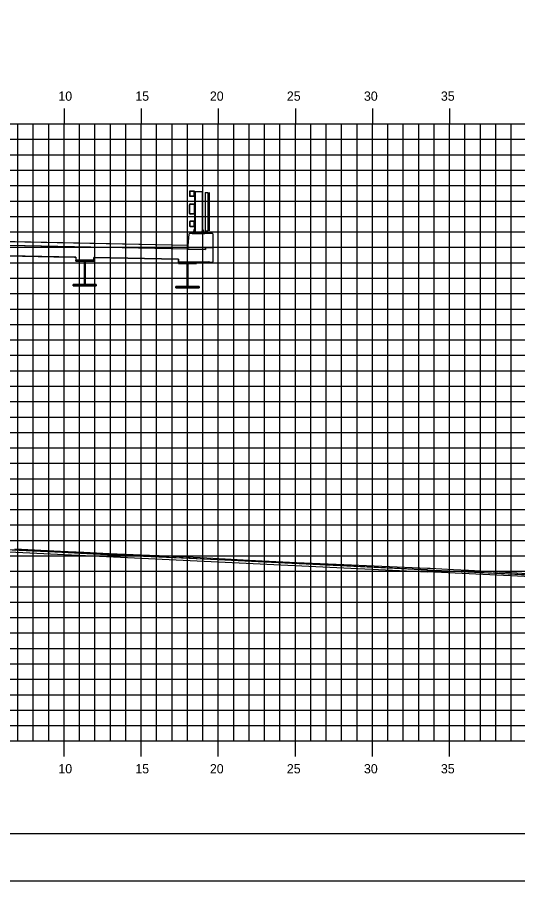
# Model space of a CAD drawing. Extents: x -22 to 1480, y -1511 to 8.
# Drawn here: x 733.2 to 765.6, y -184.5 to -128.6 of the extents above; entities that cross this region are included whole.
import ezdxf

# ---------------------------------------------------------------- set-up
doc = ezdxf.new("R2010")
doc.units = 0
for name, color, linetype in [('BORDER', 7, 'Continuous'), ('D_Bridge_Deck', 7, 'Continuous'), ('D_Bridge_Railing', 7, 'Continuous'), ('D_Bridge_Superstructure', 7, 'Continuous'), ('D_Bridge_Superstructure_Slab', 7, 'Continuous'), ('D_Roadway_Centerline', 7, 'Continuous'), ('D_Roadway_Edge_Shoulder', 7, 'Continuous'), ('D_Roadway_Edge_TW', 7, 'Continuous'), ('H_V ANNOTATION', 7, 'Continuous'), ('MAJOR', 7, 'Continuous'), ('MINOR', 7, 'Continuous'), ('PLOT BOUNDARY', 7, 'Continuous'), ('S_Roadway_Centerline', 7, 'Continuous')]:
    doc.layers.add(name, color=color, linetype=linetype)

msp = doc.modelspace()

# ---------------------------------------------------------------- linework, layer by layer
at = {"layer": 'BORDER'}
msp.add_line((651.209, -181.466), (811.209, -181.466), dxfattribs=at)
at = {"layer": 'D_Bridge_Deck'}
for p, q in [((745.376, -143.614), (745.376, -143.489)), ((745.376, -143.489), (745.834, -143.489))]:
    msp.add_line(p, q, dxfattribs=at)
for points in [[(745.834, -143.489), (745.876, -143.447), (745.876, -142.611), (745.834, -142.57), (744.334, -142.57), (744.289, -142.611), (744.209, -143.59)], [(745.584, -144.424), (744.876, -144.424), (743.626, -144.424)]]:
    msp.add_lwpolyline(points, dxfattribs=at)
at = {"layer": 'D_Bridge_Railing'}
for p, q in [((744.334, -139.861), (744.334, -140.111)), ((744.355, -139.861), (744.355, -140.111)), ((744.626, -139.82), (744.376, -139.82)), ((744.626, -139.84), (744.376, -139.84)), ((744.647, -140.111), (744.647, -139.861)), ((744.667, -140.111), (744.667, -139.861)), ((744.705, -139.861), (744.705, -142.393)), ((745.161, -139.861), (745.161, -142.393)), ((745.366, -139.903), (745.366, -142.394)), ((745.366, -139.903), (745.532, -139.903)), ((745.532, -139.903), (745.532, -142.394)), ((744.376, -140.132), (744.626, -140.132)), ((744.376, -140.153), (744.626, -140.153)), ((744.334, -141.268), (744.334, -140.705)), ((744.36, -141.268), (744.36, -140.705)), ((744.386, -140.653), (744.615, -140.653)), ((744.386, -140.679), (744.615, -140.679)), ((744.641, -140.705), (744.641, -141.268)), ((744.667, -140.705), (744.667, -141.268)), ((744.615, -141.294), (744.386, -141.294)), ((744.615, -141.32), (744.386, -141.32)), ((744.334, -141.82), (744.334, -142.07)), ((744.355, -141.82), (744.355, -142.07)), ((744.626, -141.778), (744.376, -141.778)), ((744.626, -141.799), (744.376, -141.799)), ((744.376, -142.09), (744.626, -142.09)), ((744.376, -142.111), (744.626, -142.111)), ((744.647, -142.07), (744.647, -141.82)), ((744.667, -142.07), (744.667, -141.82)), ((744.704, -142.319), (744.631, -142.319)), ((744.704, -142.328), (744.631, -142.328)), ((744.704, -142.336), (744.631, -142.336)), ((744.704, -142.344), (744.631, -142.344)), ((744.704, -142.353), (744.631, -142.353)), ((744.704, -142.361), (744.631, -142.361)), ((744.704, -142.369), (744.631, -142.369)), ((744.704, -142.377), (744.631, -142.377)), ((744.704, -142.386), (744.631, -142.386)), ((744.633, -142.401), (744.633, -142.457)), ((744.686, -142.324), (744.649, -142.324)), ((744.686, -142.332), (744.649, -142.332)), ((744.686, -142.34), (744.649, -142.34)), ((744.686, -142.348), (744.649, -142.348)), ((744.686, -142.357), (744.649, -142.357)), ((744.686, -142.365), (744.649, -142.365)), ((744.686, -142.373), (744.649, -142.373)), ((744.686, -142.382), (744.649, -142.382)), ((744.686, -142.39), (744.649, -142.39)), ((744.702, -142.401), (744.702, -142.457)), ((745.235, -142.319), (745.162, -142.319)), ((745.235, -142.328), (745.162, -142.328)), ((745.235, -142.336), (745.162, -142.336)), ((745.235, -142.344), (745.162, -142.344)), ((745.235, -142.353), (745.162, -142.353)), ((745.235, -142.361), (745.162, -142.361)), ((745.235, -142.369), (745.162, -142.369)), ((745.235, -142.377), (745.162, -142.377)), ((745.235, -142.386), (745.162, -142.386)), ((745.164, -142.401), (745.164, -142.457)), ((745.217, -142.324), (745.18, -142.324)), ((745.217, -142.332), (745.18, -142.332)), ((745.217, -142.34), (745.18, -142.34)), ((745.217, -142.348), (745.18, -142.348)), ((745.217, -142.357), (745.18, -142.357)), ((745.217, -142.365), (745.18, -142.365)), ((745.217, -142.373), (745.18, -142.373)), ((745.217, -142.382), (745.18, -142.382)), ((745.217, -142.39), (745.18, -142.39)), ((745.233, -142.401), (745.233, -142.457)), ((745.366, -142.394), (745.532, -142.394))]:
    msp.add_line(p, q, dxfattribs=at)
for points in [[(745.199, -142.311), (745.199, -139.861), (744.667, -139.861), (744.667, -142.311)], [(745.616, -139.903), (745.616, -142.394)], [(744.704, -142.393), (744.704, -142.319), (744.696, -142.311), (744.639, -142.311), (744.631, -142.319), (744.631, -142.393)], [(745.235, -142.393), (745.235, -142.319), (745.227, -142.311), (745.17, -142.311), (745.162, -142.319), (745.162, -142.393)]]:
    msp.add_lwpolyline(points, dxfattribs=at)
for points in [[(745.343, -142.478), (744.523, -142.478), (744.523, -142.56), (745.343, -142.56)], [(745.343, -142.56), (744.523, -142.56), (744.523, -142.57), (745.343, -142.57)], [(744.74, -142.478), (744.594, -142.478), (744.594, -142.465), (744.74, -142.465)], [(744.736, -142.401), (744.723, -142.393), (744.612, -142.393), (744.598, -142.401), (744.598, -142.457), (744.612, -142.465), (744.723, -142.465), (744.736, -142.457)], [(745.272, -142.478), (745.126, -142.478), (745.126, -142.465), (745.272, -142.465)], [(745.268, -142.401), (745.254, -142.393), (745.143, -142.393), (745.13, -142.401), (745.13, -142.457), (745.143, -142.465), (745.254, -142.465), (745.268, -142.457)]]:
    msp.add_lwpolyline(points, close=True, dxfattribs=at)
for centre, radius, start, end in [((744.376, -139.861), 0.0417, 90, 180), ((744.376, -139.861), 0.0208, 90, 180), ((744.626, -139.861), 0.0417, 360, 90), ((744.626, -139.861), 0.0208, 360, 90), ((744.376, -140.111), 0.0417, 180, 270), ((744.376, -140.111), 0.0208, 180, 270), ((744.626, -140.111), 0.0417, 270, 0), ((744.626, -140.111), 0.0208, 270, 0), ((744.386, -140.705), 0.052, 90, 180), ((744.386, -140.705), 0.026, 90, 180), ((744.615, -140.705), 0.052, 360, 90), ((744.615, -140.705), 0.026, 360, 90), ((744.386, -141.268), 0.052, 180, 270), ((744.386, -141.268), 0.026, 180, 270), ((744.615, -141.268), 0.052, 270, 0), ((744.615, -141.268), 0.026, 270, 0), ((744.376, -141.82), 0.0417, 90, 180), ((744.376, -142.07), 0.0417, 180, 270), ((744.376, -141.82), 0.0208, 90, 180), ((744.376, -142.07), 0.0208, 180, 270), ((744.626, -141.82), 0.0417, 360, 90), ((744.626, -141.82), 0.0208, 360, 90), ((744.626, -142.07), 0.0417, 270, 0), ((744.626, -142.07), 0.0208, 270, 0), ((744.616, -142.426), 0.0302, 55.4339, 120), ((744.616, -142.432), 0.0302, 240, 304.5661), ((744.667, -142.51), 0.114, 72.412, 107.588), ((744.667, -142.348), 0.114, 252.412, 287.588), ((744.719, -142.426), 0.0302, 60, 124.5661), ((744.719, -142.432), 0.0302, 235.4339, 300), ((745.147, -142.426), 0.0302, 55.4339, 120), ((745.147, -142.432), 0.0302, 240, 304.5661), ((745.199, -142.51), 0.114, 72.412, 107.588), ((745.199, -142.348), 0.114, 252.412, 287.588), ((745.25, -142.426), 0.0302, 60, 124.5661), ((745.25, -142.432), 0.0302, 235.4339, 300)]:
    msp.add_arc(centre, radius, start, end, dxfattribs=at)
at = {"layer": 'D_Bridge_Superstructure'}
for p, q in [((738.126, -144.29), (736.959, -144.29)), ((736.959, -144.29), (736.959, -144.374)), ((737.563, -144.374), (737.522, -144.374)), ((737.563, -144.374), (737.522, -144.374)), ((737.563, -144.374), (738.126, -144.374)), ((738.126, -144.374), (738.126, -144.29)), ((744.792, -144.424), (743.626, -144.424)), ((743.626, -144.424), (743.626, -144.507)), ((744.23, -144.507), (744.188, -144.507)), ((744.23, -144.507), (744.188, -144.507)), ((744.23, -144.507), (744.792, -144.507)), ((744.792, -144.507), (744.792, -144.424)), ((737.522, -145.874), (736.792, -145.874)), ((736.792, -145.874), (736.792, -145.957)), ((737.522, -145.874), (736.792, -145.874)), ((737.563, -145.874), (737.522, -145.874)), ((737.563, -145.874), (737.522, -145.874)), ((744.188, -146.007), (743.459, -146.007)), ((743.459, -146.007), (743.459, -146.09)), ((744.188, -146.007), (743.459, -146.007)), ((744.23, -146.007), (744.188, -146.007)), ((744.23, -146.007), (744.188, -146.007))]:
    msp.add_line(p, q, dxfattribs=at)
for points in [[(736.959, -144.29), (738.126, -144.29), (738.126, -144.374), (736.959, -144.374)], [(737.522, -144.374), (737.563, -144.374), (737.563, -145.874), (737.522, -145.874)], [(743.626, -144.424), (744.792, -144.424), (744.792, -144.507), (743.626, -144.507)], [(744.188, -144.507), (744.23, -144.507), (744.23, -146.007), (744.188, -146.007)], [(736.792, -145.874), (738.292, -145.874), (738.292, -145.957), (736.792, -145.957)], [(743.459, -146.007), (744.959, -146.007), (744.959, -146.09), (743.459, -146.09)]]:
    msp.add_lwpolyline(points, close=True, dxfattribs=at)
for points in [[(737.563, -144.374), (738.126, -144.374), (738.126, -144.29), (736.959, -144.29), (736.959, -144.374), (737.522, -144.374), (737.563, -144.374)], [(736.959, -144.374), (737.522, -144.374), (737.563, -144.374)], [(737.522, -144.374), (737.522, -145.874), (737.563, -145.874), (737.563, -144.374)], [(737.522, -144.374), (737.522, -145.874), (737.563, -145.874), (737.563, -144.374)], [(744.23, -144.507), (744.792, -144.507), (744.792, -144.424), (743.626, -144.424), (743.626, -144.507), (744.188, -144.507), (744.23, -144.507)], [(743.626, -144.507), (744.188, -144.507), (744.23, -144.507)], [(744.188, -144.507), (744.188, -146.007), (744.23, -146.007), (744.23, -144.507)], [(744.188, -144.507), (744.188, -146.007), (744.23, -146.007), (744.23, -144.507)], [(736.792, -145.874), (736.792, -145.957), (738.292, -145.957), (738.292, -145.874), (737.563, -145.874)], [(736.792, -145.957), (738.292, -145.957), (738.292, -145.874), (737.563, -145.874)], [(743.459, -146.007), (743.459, -146.09), (744.959, -146.09), (744.959, -146.007), (744.23, -146.007)], [(743.459, -146.09), (744.959, -146.09), (744.959, -146.007), (744.23, -146.007)]]:
    msp.add_lwpolyline(points, dxfattribs=at)
at = {"layer": 'D_Bridge_Superstructure_Slab'}
for points in [[(745.834, -142.57), (744.334, -142.57), (744.289, -142.611), (744.209, -143.59), (745.376, -143.614), (745.376, -143.489), (745.834, -143.489), (745.876, -143.447), (745.876, -142.611)], [(744.231, -143.32), (744.209, -143.59), (726.209, -143.23), (704.209, -143.67), (704.187, -143.4), (726.209, -142.96)]]:
    msp.add_lwpolyline(points, close=True, dxfattribs=at)
for points in [[(745.376, -143.614), (726.209, -143.23), (703.042, -143.694)], [(731.459, -144.002), (735.542, -144.084), (736.876, -144.11), (736.959, -144.112), (736.959, -144.29), (738.126, -144.29), (738.126, -144.135), (743.626, -144.245), (743.626, -144.424), (745.584, -144.424), (745.626, -144.382), (745.626, -144.424), (745.834, -144.424), (745.876, -144.382), (745.876, -143.53), (745.834, -143.489), (745.376, -143.489), (745.376, -143.614), (726.209, -143.23)], [(744.209, -143.59), (735.709, -143.42)], [(745.626, -144.424), (745.834, -144.424), (745.876, -144.382), (745.876, -143.53), (745.834, -143.489)], [(736.959, -144.112), (731.459, -144.002)], [(736.959, -144.112), (736.959, -144.29), (738.126, -144.29), (738.126, -144.135)], [(743.626, -144.424), (743.626, -144.245), (738.126, -144.135)], [(745.626, -144.424), (745.626, -144.382), (745.584, -144.424)]]:
    msp.add_lwpolyline(points, dxfattribs=at)
at = {"layer": 'D_Roadway_Centerline'}
for points in [[(704.187, -143.4), (709.209, -143.3), (714.209, -143.2), (719.969, -143.084), (726.209, -142.96), (731.969, -143.075), (738.209, -143.2), (741.209, -143.26), (744.231, -143.32)], [(731.88, -163.036), (736.06, -163.231), (738.093, -163.328), (741.347, -163.481), (744.309, -163.623), (746.633, -163.733), (750.528, -163.921), (751.919, -163.987), (756.749, -164.221), (757.206, -164.243), (759.781, -164.368), (762.492, -164.501), (763.928, -164.572), (767.779, -164.761)]]:
    msp.add_lwpolyline(points, dxfattribs=at)
at = {"layer": 'D_Roadway_Edge_Shoulder'}
msp.add_lwpolyline([(759.781, -164.368), (775.051, -165.122), (775.051, -165.247), (759.781, -164.493)], close=True, dxfattribs=at)
at = {"layer": 'D_Roadway_Edge_TW'}
msp.add_lwpolyline([(759.781, -164.493), (759.781, -164.368), (724.445, -162.689), (691.239, -161.774), (691.239, -161.899), (724.445, -162.814)], close=True, dxfattribs=at)
at = {"layer": 'MAJOR'}
for p, q in [((736.209, -134.464), (736.209, -135.466)), ((741.209, -134.464), (741.209, -135.466)), ((746.209, -134.464), (746.209, -135.466)), ((751.209, -134.464), (751.209, -135.466)), ((756.209, -134.464), (756.209, -135.466)), ((761.209, -134.464), (761.209, -135.466)), ((656.209, -135.466), (796.209, -135.466)), ((656.209, -135.466), (796.209, -135.466)), ((736.209, -175.466), (736.209, -135.466)), ((741.209, -175.466), (741.209, -135.466)), ((746.209, -175.466), (746.209, -135.466)), ((751.209, -175.466), (751.209, -135.466)), ((756.209, -175.466), (756.209, -135.466)), ((761.209, -175.466), (761.209, -135.466)), ((656.209, -140.466), (796.209, -140.466)), ((656.209, -145.466), (796.209, -145.466)), ((656.209, -150.466), (796.209, -150.466)), ((656.209, -155.466), (796.209, -155.466)), ((656.209, -160.466), (796.209, -160.466)), ((656.209, -165.466), (796.209, -165.466)), ((656.209, -170.466), (796.209, -170.466)), ((656.209, -175.466), (796.209, -175.466)), ((656.209, -175.466), (796.209, -175.466)), ((736.209, -176.468), (736.209, -175.466)), ((741.209, -176.468), (741.209, -175.466)), ((746.209, -176.468), (746.209, -175.466)), ((751.209, -176.468), (751.209, -175.466)), ((756.209, -176.468), (756.209, -175.466)), ((761.209, -176.468), (761.209, -175.466))]:
    msp.add_line(p, q, dxfattribs=at)
at = {"layer": 'MINOR'}
for p, q in [((733.209, -175.466), (733.209, -135.466)), ((734.209, -175.466), (734.209, -135.466)), ((735.209, -175.466), (735.209, -135.466)), ((737.209, -175.466), (737.209, -135.466)), ((738.209, -175.466), (738.209, -135.466)), ((739.209, -175.466), (739.209, -135.466)), ((740.209, -175.466), (740.209, -135.466)), ((742.209, -175.466), (742.209, -135.466)), ((743.209, -175.466), (743.209, -135.466)), ((744.209, -175.466), (744.209, -135.466)), ((745.209, -175.466), (745.209, -135.466)), ((747.209, -175.466), (747.209, -135.466)), ((748.209, -175.466), (748.209, -135.466)), ((749.209, -175.466), (749.209, -135.466)), ((750.209, -175.466), (750.209, -135.466)), ((752.209, -175.466), (752.209, -135.466)), ((753.209, -175.466), (753.209, -135.466)), ((754.209, -175.466), (754.209, -135.466)), ((755.209, -175.466), (755.209, -135.466)), ((757.209, -175.466), (757.209, -135.466)), ((758.209, -175.466), (758.209, -135.466)), ((759.209, -175.466), (759.209, -135.466)), ((760.209, -175.466), (760.209, -135.466)), ((762.209, -175.466), (762.209, -135.466)), ((763.209, -175.466), (763.209, -135.466)), ((764.209, -175.466), (764.209, -135.466)), ((765.209, -175.466), (765.209, -135.466)), ((656.209, -136.466), (796.209, -136.466)), ((656.209, -137.466), (796.209, -137.466)), ((656.209, -138.466), (796.209, -138.466)), ((656.209, -139.466), (796.209, -139.466)), ((656.209, -141.466), (796.209, -141.466)), ((656.209, -142.466), (796.209, -142.466)), ((656.209, -143.466), (796.209, -143.466)), ((656.209, -144.466), (796.209, -144.466)), ((656.209, -146.466), (796.209, -146.466)), ((656.209, -147.466), (796.209, -147.466)), ((656.209, -148.466), (796.209, -148.466)), ((656.209, -149.466), (796.209, -149.466)), ((656.209, -151.466), (796.209, -151.466)), ((656.209, -152.466), (796.209, -152.466)), ((656.209, -153.466), (796.209, -153.466)), ((656.209, -154.466), (796.209, -154.466)), ((656.209, -156.466), (796.209, -156.466)), ((656.209, -157.466), (796.209, -157.466)), ((656.209, -158.466), (796.209, -158.466)), ((656.209, -159.466), (796.209, -159.466)), ((656.209, -161.466), (796.209, -161.466)), ((656.209, -162.466), (796.209, -162.466)), ((656.209, -163.466), (796.209, -163.466)), ((656.209, -164.466), (796.209, -164.466)), ((656.209, -166.466), (796.209, -166.466)), ((656.209, -167.466), (796.209, -167.466)), ((656.209, -168.466), (796.209, -168.466)), ((656.209, -169.466), (796.209, -169.466)), ((656.209, -171.466), (796.209, -171.466)), ((656.209, -172.466), (796.209, -172.466)), ((656.209, -173.466), (796.209, -173.466)), ((656.209, -174.466), (796.209, -174.466))]:
    msp.add_line(p, q, dxfattribs=at)
at = {"layer": 'PLOT BOUNDARY'}
msp.add_lwpolyline([(643.116, -184.525), (813.116, -184.525), (813.116, -74.525), (643.116, -74.525)], close=True, dxfattribs=at)
at = {"layer": 'S_Roadway_Centerline'}
msp.add_lwpolyline([(733.019, -163.022), (735.973, -163.156), (737.484, -163.227), (739.136, -163.303), (742.269, -163.445), (742.301, -163.446), (742.363, -163.449), (745.464, -163.605), (747.051, -163.681), (748.627, -163.762), (751.707, -163.919), (751.781, -163.922), (753.863, -164.004), (759.781, -164.263), (759.876, -164.268), (759.944, -164.272), (761.475, -164.355), (762.439, -164.404), (765.226, -164.543), (767.59, -164.704)], dxfattribs=at)

# ---------------------------------------------------------------- texts
at = {"layer": 'H_V ANNOTATION'}
for s, p in [('10', (735.834, -133.966)), ('15', (740.826, -133.966)), ('20', (745.663, -133.966)), ('25', (750.655, -133.966)), ('30', (755.657, -133.966)), ('35', (760.649, -133.966)), ('10', (735.834, -177.566)), ('15', (740.826, -177.566)), ('20', (745.663, -177.566)), ('25', (750.655, -177.566)), ('30', (755.657, -177.566)), ('35', (760.649, -177.566))]:
    msp.add_text(s, height=0.6, dxfattribs=at).set_placement(p)

doc.saveas('drawing.dxf')
